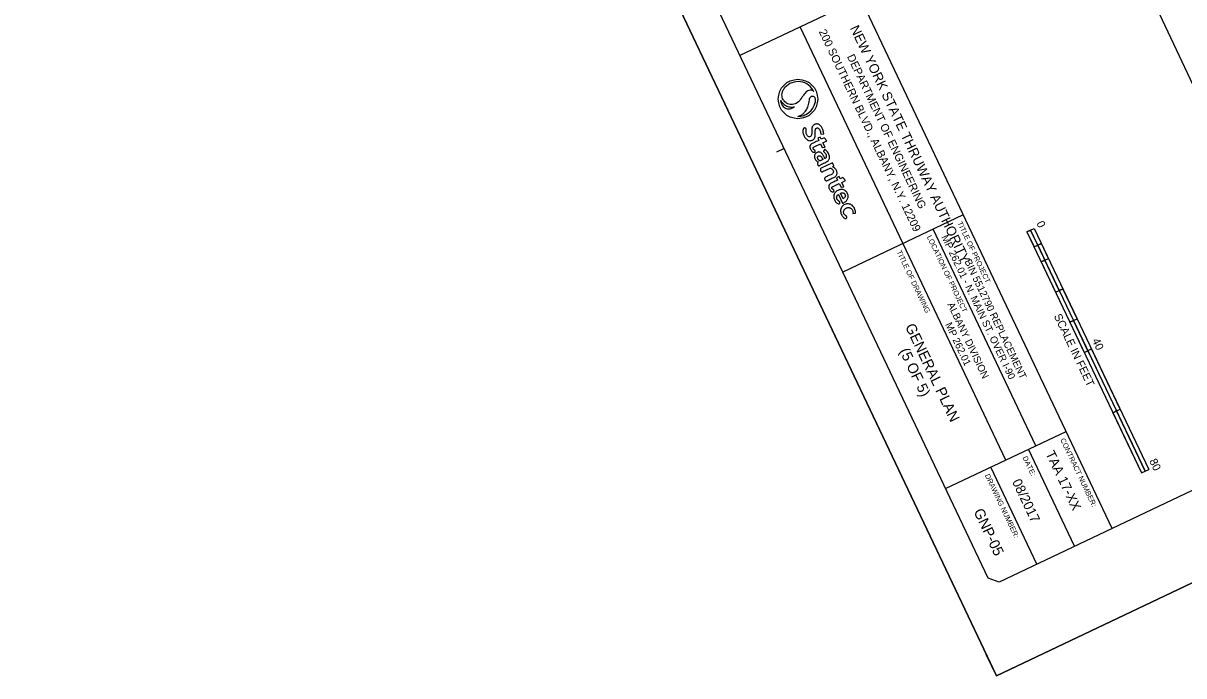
# Model space of a CAD drawing. Extents: x 1041072 to 1041761, y 1125784 to 1126587.
# Drawn here: x 1041071.6 to 1041419.5, y 1125783.8 to 1125979.4 of the extents above; entities that cross this region are included whole.
import ezdxf

# ---------------------------------------------------------------- set-up
doc = ezdxf.new("R2010")
doc.units = 0
for name, color, linetype in [('clip boundary', 7, 'Continuous'), ('G-ANNO-LOGO', 7, 'Continuous'), ('NSB_P', 7, 'Continuous'), ('O_Details_Text Title and Subtitle Proposed_P_T', 7, 'Continuous'), ('SHEET_BORDER', 7, 'Continuous'), ('SHEET_BORDER_CUT', 7, 'Continuous'), ('SHEET_BORDER_TEXT', 7, 'Continuous')]:
    doc.layers.add(name, color=color, linetype=linetype)

msp = doc.modelspace()

# ---------------------------------------------------------------- linework, layer by layer
at = {"layer": 'clip boundary'}
for points in [[(1041469.06, 1126586.8), (1041760.77, 1125972.54), (1041363.32, 1125783.79), (1041071.61, 1126398.04)], [(1041436.47, 1126509.64), (1041674.33, 1125994.72), (1041455.4, 1125890.75), (1041213.53, 1126403.1)]]:
    msp.add_lwpolyline(points, close=True, dxfattribs=at)
at = {"layer": 'G-ANNO-LOGO'}
for p, q in [((1041308.75, 1125942.33), (1041310.61, 1125943.2)), ((1041310.52, 1125945.25), (1041309.79, 1125944.91)), ((1041309.79, 1125944.91), (1041310.11, 1125944.23)), ((1041310.84, 1125944.59), (1041310.52, 1125945.25)), ((1041310.61, 1125943.2), (1041311.13, 1125942.09)), ((1041310.69, 1125946.11), (1041311.56, 1125946.21)), ((1041311.71, 1125945), (1041310.84, 1125944.59)), ((1041311.34, 1125943.54), (1041312.51, 1125944.09)), ((1041311.98, 1125942.18), (1041311.34, 1125943.54)), ((1041312.51, 1125944.09), (1041311.71, 1125945)), ((1041311.13, 1125942.09), (1041311.98, 1125942.18)), ((1041311.93, 1125941.61), (1041311.46, 1125941)), ((1041311.3, 1125938.5), (1041310.47, 1125938.11)), ((1041314.2, 1125937.51), (1041310.85, 1125935.92)), ((1041311.34, 1125934.9), (1041313.55, 1125935.95)), ((1041314.62, 1125936.63), (1041314.2, 1125937.51)), ((1041314.2, 1125936.36), (1041314.62, 1125936.63)), ((1041316.16, 1125933.39), (1041315.43, 1125933.04)), ((1041315.43, 1125933.04), (1041315.75, 1125932.37)), ((1041316.48, 1125932.72), (1041316.16, 1125933.39)), ((1041317.35, 1125933.14), (1041316.48, 1125932.72)), ((1041318.14, 1125932.22), (1041317.35, 1125933.14)), ((1041314.39, 1125930.47), (1041316.24, 1125931.33)), ((1041316.24, 1125931.33), (1041316.77, 1125930.22)), ((1041316.77, 1125930.22), (1041317.62, 1125930.31)), ((1041316.97, 1125931.67), (1041318.14, 1125932.22)), ((1041317.62, 1125930.31), (1041316.97, 1125931.67)), ((1041315.98, 1125928.07), (1041317.25, 1125925.41)), ((1041317.39, 1125926.78), (1041316.63, 1125928.38)), ((1041320.31, 1125922.31), (1041321.11, 1125922.4))]:
    msp.add_line(p, q, dxfattribs=at)
for points in [[(1041308.61, 1125958.79), (1041308.61, 1125958.79)], [(1041308.97, 1125955.65), (1041308.96, 1125955.65)]]:
    msp.add_lwpolyline(points, dxfattribs=at)
msp.add_circle((1041303.86, 1125956.65), 5.91, dxfattribs=at)
for start, end in [(24.1697, 139.0876), (24.1633, 24.1697), (182.5216, 186.8611), (269.1846, 348.8358)]:
    msp.add_arc((1041303.86, 1125956.65), 5.21, start, end, dxfattribs=at)
for points, degree in [([(1041308.61, 1125958.79), (1041308.53, 1125958.89), (1041308.35, 1125959.13), (1041307.82, 1125959.31), (1041307.12, 1125959.29), (1041306.48, 1125958.94), (1041305.95, 1125958.41), (1041305.5, 1125957.77), (1041304.99, 1125957.08), (1041304.54, 1125956.37), (1041304.02, 1125955.78), (1041303.37, 1125955.31), (1041302.62, 1125955.06), (1041301.87, 1125954.96), (1041301.09, 1125955.08), (1041300.42, 1125955.41), (1041299.91, 1125955.84), (1041299.52, 1125956.27), (1041299.25, 1125956.82), (1041299.05, 1125957.48), (1041299.04, 1125958.23), (1041299.28, 1125959.14), (1041299.67, 1125959.71), (1041299.92, 1125960.06)], 3), ([(1041303.78, 1125951.45), (1041303.97, 1125951.49), (1041304.31, 1125951.56), (1041304.8, 1125951.81), (1041305.22, 1125952.07), (1041305.56, 1125952.39), (1041305.96, 1125952.76), (1041306.34, 1125953.27), (1041306.64, 1125953.88), (1041306.91, 1125954.61), (1041307.06, 1125955.44), (1041307.28, 1125956.33), (1041307.42, 1125957.02), (1041307.79, 1125957.41), (1041308.13, 1125957.58), (1041308.44, 1125957.52), (1041308.71, 1125957.37), (1041308.88, 1125957.08), (1041308.98, 1125956.69), (1041309, 1125956.2), (1041308.98, 1125955.84), (1041308.97, 1125955.65)], 3), ([(1041308.61, 1125958.79), (1041308.61, 1125958.79), (1041308.61, 1125958.79), (1041308.61, 1125958.79)], 2), ([(1041298.66, 1125956.43), (1041298.7, 1125956.3), (1041298.8, 1125956.02), (1041299.11, 1125955.6), (1041299.48, 1125955.13), (1041299.98, 1125954.8), (1041300.49, 1125954.51), (1041301.11, 1125954.31), (1041301.76, 1125954.2), (1041302.36, 1125954.23), (1041302.69, 1125954.31), (1041302.85, 1125954.34)], 3), ([(1041302.85, 1125954.34), (1041302.74, 1125954.25), (1041302.48, 1125954.02), (1041301.98, 1125953.75), (1041301.38, 1125953.58), (1041300.75, 1125953.62), (1041300.1, 1125953.79), (1041299.58, 1125954.23), (1041299.17, 1125954.76), (1041298.87, 1125955.36), (1041298.75, 1125955.82), (1041298.69, 1125956.03)], 3), ([(1041311.56, 1125946.21), (1041311.56, 1125946.26), (1041311.56, 1125946.52), (1041311.47, 1125946.96), (1041311.3, 1125947.48), (1041311.12, 1125947.93), (1041310.9, 1125948.28), (1041310.66, 1125948.6), (1041310.37, 1125948.87), (1041309.99, 1125949.09), (1041309.58, 1125949.19), (1041309.21, 1125949.17), (1041308.91, 1125949.07), (1041308.66, 1125948.93), (1041308.44, 1125948.76), (1041308.28, 1125948.56), (1041308.15, 1125948.34), (1041308.06, 1125948.1), (1041308, 1125947.84), (1041307.97, 1125947.53), (1041307.96, 1125947.17), (1041307.96, 1125946.78), (1041307.98, 1125946.38), (1041307.97, 1125946.04), (1041307.89, 1125945.76), (1041307.8, 1125945.55), (1041307.62, 1125945.41), (1041307.44, 1125945.33), (1041307.2, 1125945.3), (1041306.94, 1125945.39), (1041306.7, 1125945.61), (1041306.5, 1125945.91), (1041306.35, 1125946.27), (1041306.26, 1125946.61), (1041306.27, 1125946.92), (1041306.26, 1125947.17), (1041306.32, 1125947.37), (1041306.31, 1125947.52), (1041306.3, 1125947.67), (1041306.23, 1125947.79), (1041306.13, 1125947.9), (1041305.99, 1125947.97), (1041305.81, 1125947.98), (1041305.66, 1125947.91), (1041305.53, 1125947.82), (1041305.43, 1125947.63), (1041305.31, 1125947.3), (1041305.3, 1125946.81), (1041305.4, 1125946.26), (1041305.61, 1125945.75), (1041305.83, 1125945.33), (1041306.05, 1125944.98), (1041306.31, 1125944.7), (1041306.62, 1125944.43), (1041307.04, 1125944.23), (1041307.48, 1125944.13), (1041307.9, 1125944.2), (1041308.25, 1125944.35), (1041308.54, 1125944.53), (1041308.73, 1125944.77), (1041308.91, 1125945.04), (1041308.99, 1125945.39), (1041309.05, 1125945.77), (1041309.05, 1125946.16), (1041309.05, 1125946.59), (1041309.03, 1125947.02), (1041309.05, 1125947.4), (1041309.14, 1125947.69), (1041309.28, 1125947.87), (1041309.46, 1125947.97), (1041309.66, 1125948), (1041309.87, 1125947.95), (1041310.05, 1125947.84), (1041310.23, 1125947.66), (1041310.38, 1125947.41), (1041310.49, 1125947.15), (1041310.57, 1125946.88), (1041310.63, 1125946.61), (1041310.67, 1125946.35), (1041310.68, 1125946.19), (1041310.69, 1125946.11)], 3), ([(1041310.11, 1125944.23), (1041309.46, 1125943.93), (1041308.77, 1125943.6), (1041308.01, 1125943.23), (1041307.84, 1125943.11), (1041307.62, 1125942.92), (1041307.52, 1125942.69), (1041307.45, 1125942.48), (1041307.42, 1125942.28), (1041307.45, 1125942), (1041307.58, 1125941.65), (1041307.76, 1125941.31), (1041307.97, 1125940.98), (1041308.23, 1125940.78), (1041308.48, 1125940.66), (1041308.7, 1125940.66), (1041308.86, 1125940.72), (1041308.98, 1125940.81), (1041309.03, 1125940.92), (1041309.04, 1125941.03), (1041309.01, 1125941.14), (1041308.96, 1125941.24), (1041308.88, 1125941.33), (1041308.76, 1125941.39), (1041308.63, 1125941.46), (1041308.51, 1125941.56), (1041308.41, 1125941.68), (1041308.35, 1125941.83), (1041308.36, 1125941.98), (1041308.41, 1125942.13), (1041308.56, 1125942.25), (1041308.68, 1125942.3), (1041308.75, 1125942.33)], 3), ([(1041311.91, 1125938.8), (1041311.88, 1125938.87), (1041311.77, 1125939.09), (1041311.57, 1125939.46), (1041311.34, 1125939.9), (1041311.04, 1125940.28), (1041310.69, 1125940.59), (1041310.24, 1125940.79), (1041309.75, 1125940.76), (1041309.37, 1125940.55), (1041309.06, 1125940.33), (1041308.87, 1125939.99), (1041308.76, 1125939.57), (1041308.8, 1125939.07), (1041309, 1125938.63), (1041309.25, 1125938.25), (1041309.5, 1125937.99), (1041309.77, 1125937.84), (1041309.92, 1125937.79), (1041310, 1125937.76)], 3), ([(1041310, 1125937.76), (1041309.96, 1125937.74), (1041309.88, 1125937.69), (1041309.79, 1125937.55), (1041309.71, 1125937.36), (1041309.71, 1125937.08), (1041309.83, 1125936.85), (1041309.98, 1125936.65), (1041310.2, 1125936.65), (1041310.37, 1125936.73), (1041310.58, 1125936.89), (1041311.2, 1125937.25), (1041311.9, 1125937.53), (1041312.63, 1125937.89), (1041312.94, 1125938.14), (1041313.17, 1125938.5), (1041313.31, 1125938.83), (1041313.32, 1125939.27), (1041313.23, 1125939.76), (1041313.01, 1125940.3), (1041312.71, 1125940.8), (1041312.35, 1125941.25), (1041312.06, 1125941.5), (1041311.93, 1125941.61)], 3), ([(1041310.47, 1125938.11), (1041310.44, 1125938.13), (1041310.32, 1125938.19), (1041310.13, 1125938.32), (1041309.91, 1125938.52), (1041309.77, 1125938.78), (1041309.72, 1125939.04), (1041309.75, 1125939.24), (1041309.82, 1125939.41), (1041309.94, 1125939.55), (1041310.09, 1125939.63), (1041310.26, 1125939.68), (1041310.46, 1125939.65), (1041310.63, 1125939.54), (1041310.81, 1125939.39), (1041310.96, 1125939.15), (1041311.1, 1125938.9), (1041311.22, 1125938.67), (1041311.28, 1125938.55), (1041311.3, 1125938.5)], 3), ([(1041311.46, 1125941), (1041311.51, 1125940.96), (1041311.65, 1125940.85), (1041311.84, 1125940.65), (1041312.05, 1125940.4), (1041312.2, 1125940.14), (1041312.32, 1125939.85), (1041312.36, 1125939.56), (1041312.34, 1125939.28), (1041312.23, 1125939.03), (1041312.07, 1125938.87), (1041311.95, 1125938.82), (1041311.91, 1125938.8)], 3), ([(1041310.85, 1125935.92), (1041310.81, 1125935.89), (1041310.72, 1125935.83), (1041310.58, 1125935.67), (1041310.53, 1125935.41), (1041310.65, 1125935.15), (1041310.8, 1125934.9), (1041311.04, 1125934.82), (1041311.22, 1125934.84), (1041311.3, 1125934.88), (1041311.34, 1125934.9)], 3), ([(1041313.55, 1125935.95), (1041313.57, 1125935.94), (1041313.67, 1125935.89), (1041313.86, 1125935.77), (1041314.11, 1125935.62), (1041314.33, 1125935.38), (1041314.46, 1125935.09), (1041314.51, 1125934.77), (1041314.4, 1125934.48), (1041314.21, 1125934.27), (1041313.92, 1125934.06), (1041313.43, 1125933.87), (1041312.83, 1125933.56), (1041312.31, 1125933.35), (1041311.98, 1125933.17), (1041311.85, 1125932.96), (1041311.81, 1125932.68), (1041311.93, 1125932.44), (1041312.1, 1125932.24), (1041312.33, 1125932.12), (1041312.63, 1125932.19), (1041313.1, 1125932.47), (1041313.71, 1125932.72), (1041314.36, 1125933.05), (1041314.79, 1125933.23), (1041315.13, 1125933.45), (1041315.33, 1125933.69), (1041315.51, 1125933.99), (1041315.57, 1125934.38), (1041315.57, 1125934.83), (1041315.39, 1125935.26), (1041315.18, 1125935.62), (1041314.91, 1125935.91), (1041314.63, 1125936.14), (1041314.37, 1125936.27), (1041314.24, 1125936.34), (1041314.2, 1125936.36)], 3), ([(1041315.75, 1125932.37), (1041315.09, 1125932.06), (1041314.41, 1125931.74), (1041313.64, 1125931.36), (1041313.47, 1125931.24), (1041313.26, 1125931.05), (1041313.15, 1125930.83), (1041313.09, 1125930.62), (1041313.06, 1125930.42), (1041313.09, 1125930.13), (1041313.21, 1125929.78), (1041313.39, 1125929.44), (1041313.6, 1125929.12), (1041313.86, 1125928.92), (1041314.11, 1125928.8), (1041314.33, 1125928.79), (1041314.5, 1125928.86), (1041314.62, 1125928.95), (1041314.66, 1125929.06), (1041314.67, 1125929.16), (1041314.64, 1125929.27), (1041314.59, 1125929.37), (1041314.52, 1125929.47), (1041314.4, 1125929.52), (1041314.27, 1125929.59), (1041314.15, 1125929.7), (1041314.04, 1125929.81), (1041313.99, 1125929.96), (1041314, 1125930.12), (1041314.05, 1125930.26), (1041314.19, 1125930.38), (1041314.31, 1125930.43), (1041314.39, 1125930.47)], 3), ([(1041317.25, 1125925.41), (1041317.35, 1125925.45), (1041317.61, 1125925.56), (1041318, 1125925.8), (1041318.41, 1125926.13), (1041318.66, 1125926.52), (1041318.85, 1125926.91), (1041318.92, 1125927.33), (1041318.89, 1125927.81), (1041318.7, 1125928.28), (1041318.48, 1125928.72), (1041318.15, 1125929.07), (1041317.77, 1125929.34), (1041317.32, 1125929.51), (1041316.86, 1125929.55), (1041316.41, 1125929.48), (1041315.98, 1125929.34), (1041315.54, 1125929.13), (1041315.18, 1125928.85), (1041314.87, 1125928.5), (1041314.65, 1125928.1), (1041314.55, 1125927.6), (1041314.55, 1125927.03), (1041314.77, 1125926.48), (1041315.01, 1125925.99), (1041315.29, 1125925.62), (1041315.61, 1125925.37), (1041315.93, 1125925.23), (1041316.19, 1125925.25), (1041316.36, 1125925.37), (1041316.46, 1125925.53), (1041316.43, 1125925.69), (1041316.38, 1125925.84), (1041316.25, 1125925.98), (1041316.04, 1125926.12), (1041315.8, 1125926.28), (1041315.61, 1125926.52), (1041315.49, 1125926.77), (1041315.43, 1125927.05), (1041315.48, 1125927.32), (1041315.55, 1125927.6), (1041315.71, 1125927.83), (1041315.86, 1125927.99), (1041315.95, 1125928.05), (1041315.98, 1125928.07)], 3), ([(1041316.63, 1125928.38), (1041316.66, 1125928.39), (1041316.74, 1125928.43), (1041316.9, 1125928.5), (1041317.13, 1125928.54), (1041317.4, 1125928.52), (1041317.66, 1125928.4), (1041317.88, 1125928.18), (1041318.02, 1125927.9), (1041318.07, 1125927.6), (1041318.03, 1125927.3), (1041317.84, 1125927.07), (1041317.62, 1125926.9), (1041317.46, 1125926.81), (1041317.39, 1125926.78)], 3), ([(1041321.11, 1125922.4), (1041321.11, 1125922.51), (1041321.13, 1125922.79), (1041321.04, 1125923.27), (1041320.84, 1125923.82), (1041320.51, 1125924.36), (1041320.08, 1125924.81), (1041319.57, 1125925.12), (1041319.01, 1125925.25), (1041318.45, 1125925.22), (1041317.89, 1125925.05), (1041317.39, 1125924.75), (1041317, 1125924.35), (1041316.76, 1125923.91), (1041316.62, 1125923.39), (1041316.63, 1125922.77), (1041316.81, 1125922.12), (1041317.11, 1125921.6), (1041317.44, 1125921.2), (1041317.78, 1125920.92), (1041318.11, 1125920.79), (1041318.33, 1125920.88), (1041318.48, 1125920.98), (1041318.53, 1125921.13), (1041318.54, 1125921.27), (1041318.49, 1125921.4), (1041318.39, 1125921.55), (1041318.19, 1125921.64), (1041318, 1125921.81), (1041317.8, 1125921.97), (1041317.63, 1125922.26), (1041317.51, 1125922.59), (1041317.53, 1125922.98), (1041317.65, 1125923.32), (1041317.84, 1125923.63), (1041318.14, 1125923.84), (1041318.44, 1125924.04), (1041318.81, 1125924.1), (1041319.16, 1125924.12), (1041319.48, 1125924.05), (1041319.77, 1125923.89), (1041320.01, 1125923.66), (1041320.19, 1125923.34), (1041320.32, 1125923), (1041320.37, 1125922.64), (1041320.33, 1125922.41), (1041320.31, 1125922.31)], 3)]:
    msp.add_open_spline(points, degree=degree, dxfattribs=at)
at = {"layer": 'NSB_P'}
for p, q in [((1041372.51, 1125916.84), (1041374.68, 1125917.87)), ((1041373.59, 1125917.35), (1041372.51, 1125916.84)), ((1041372.51, 1125916.84), (1041406.83, 1125844.57)), ((1041372.51, 1125916.84), (1041374.66, 1125912.32)), ((1041373.59, 1125917.35), (1041407.91, 1125845.09)), ((1041375.74, 1125912.84), (1041373.59, 1125917.35)), ((1041374.68, 1125917.87), (1041409, 1125845.6)), ((1041374.66, 1125912.32), (1041376.82, 1125913.35)), ((1041374.66, 1125912.32), (1041375.74, 1125912.84)), ((1041376.82, 1125913.35), (1041375.74, 1125912.84)), ((1041375.74, 1125912.84), (1041377.88, 1125908.32)), ((1041378.97, 1125908.83), (1041376.82, 1125913.35)), ((1041376.8, 1125907.8), (1041378.97, 1125908.83)), ((1041377.88, 1125908.32), (1041376.8, 1125907.8)), ((1041377.88, 1125908.32), (1041378.97, 1125908.83)), ((1041382.17, 1125899.29), (1041377.88, 1125908.32)), ((1041376.8, 1125907.8), (1041381.09, 1125898.77)), ((1041381.09, 1125898.77), (1041383.26, 1125899.8)), ((1041381.09, 1125898.77), (1041382.17, 1125899.29)), ((1041383.26, 1125899.8), (1041382.17, 1125899.29)), ((1041382.17, 1125899.29), (1041386.46, 1125890.25)), ((1041387.55, 1125890.77), (1041383.26, 1125899.8)), ((1041385.38, 1125889.74), (1041387.55, 1125890.77)), ((1041386.46, 1125890.25), (1041387.55, 1125890.77)), ((1041386.46, 1125890.25), (1041385.38, 1125889.74)), ((1041385.38, 1125889.74), (1041389.67, 1125880.7)), ((1041390.75, 1125881.22), (1041386.46, 1125890.25)), ((1041389.67, 1125880.7), (1041391.84, 1125881.73)), ((1041389.67, 1125880.7), (1041390.75, 1125881.22)), ((1041391.84, 1125881.73), (1041390.75, 1125881.22)), ((1041390.75, 1125881.22), (1041399.33, 1125863.15)), ((1041400.42, 1125863.67), (1041391.84, 1125881.73)), ((1041398.25, 1125862.64), (1041400.42, 1125863.67)), ((1041399.33, 1125863.15), (1041398.25, 1125862.64)), ((1041399.33, 1125863.15), (1041400.42, 1125863.67)), ((1041407.91, 1125845.09), (1041399.33, 1125863.15)), ((1041398.25, 1125862.64), (1041406.83, 1125844.57)), ((1041406.83, 1125844.57), (1041409, 1125845.6)), ((1041406.83, 1125844.57), (1041407.91, 1125845.09))]:
    msp.add_line(p, q, dxfattribs=at)
at = {"layer": 'SHEET_BORDER'}
for p, q in [((1041398.04, 1125827.96), (1041253.98, 1126131.3)), ((1041322.56, 1125986.88), (1041286.43, 1125969.72)), ((1041366.16, 1125848.45), (1041304.5, 1125978.3)), ((1041299.7, 1125941.78), (1041297.45, 1125940.7)), ((1041353.4, 1125921.96), (1041317.26, 1125904.8)), ((1041375.2, 1125852.74), (1041344.36, 1125917.67)), ((1041348.1, 1125839.87), (1041384.23, 1125857.03)), ((1041386.75, 1125822.59), (1041372.94, 1125851.67)), ((1041375.46, 1125817.23), (1041361.65, 1125846.31))]:
    msp.add_line(p, q, dxfattribs=at)
msp.add_lwpolyline([(1041364.16, 1125811.87), (1041360.83, 1125813.06), (1041092.72, 1126377.63), (1041093.9, 1126380.96), (1041468.21, 1126558.72), (1041471.54, 1126557.53), (1041739.66, 1125992.96), (1041738.47, 1125989.63)], close=True, dxfattribs=at)
at = {"layer": 'SHEET_BORDER_CUT'}
msp.add_lwpolyline([(1041071.61, 1126398.04), (1041363.32, 1125783.79), (1041760.77, 1125972.54), (1041469.06, 1126586.8)], close=True, dxfattribs=at)
msp.add_lwpolyline([(1041369.7, 1125786.82), (1041363.32, 1125783.79), (1041360.28, 1125790.18)], dxfattribs=at)
at = {"layer": 'SHEET_BORDER_TEXT'}
msp.add_line((1041363.32, 1125783.79), (1041363.32, 1125783.79), dxfattribs=at)

# ---------------------------------------------------------------- texts
at = {"layer": 'NSB_P'}
for s, p in [('0', (1041375.27, 1125919.41)), ('SCALE IN FEET', (1041380.51, 1125891.6)), ('40', (1041391.94, 1125884.31)), ('80', (1041409.1, 1125848.18))]:
    msp.add_text(s, height=2.4, rotation=295.4032, dxfattribs=at).set_placement(p)
at = {"layer": 'O_Details_Text Title and Subtitle Proposed_P_T'}
for s, height, p in [('GENERAL PLAN', 3.1248, (1041335.91, 1125888.47)), ('(5 OF 5)', 3.125, (1041334.19, 1125881.15)), ('GNP-05', 3.125, (1041356.43, 1125833.03))]:
    msp.add_text(s, height=height, rotation=295.4032, dxfattribs=at).set_placement(p)
at = {"layer": 'SHEET_BORDER'}
for s, height, p in [('200 SOUTHERN BLVD., ALBANY, N.Y. 12209', 2.4, (1041310.03, 1125976.86)), ('NEW YORK STATE THRUWAY AUTHORITY', 2.88, (1041319.37, 1125977.91)), ('DEPARTMENT OF ENGINEERING', 2.4, (1041318.48, 1125969.38)), ('TITLE OF PROJECT', 1.5625, (1041351.58, 1125919.5)), ('LOCATION OF PROJECT', 1.5625, (1041342.44, 1125915.35)), ('TITLE OF DRAWING', 1.5625, (1041333.37, 1125910.85)), ('CONTRACT NUMBER:', 1.5625, (1041382.42, 1125854.57)), ('DATE:', 1.562, (1041371.12, 1125849.21)), ('DRAWING NUMBER:', 1.5625, (1041359.83, 1125843.85))]:
    msp.add_text(s, height=height, rotation=295.4032, dxfattribs=at).set_placement(p)
at = {"layer": 'SHEET_BORDER_TEXT'}
for s, height, p in [('MP 262.01 - N. MAIN ST. OVER I-90', 2.16, (1041346.8, 1125915.3)), ('BIN 5512790 REPLACEMENT', 2.16, (1041353.71, 1125908)), ('ALBANY DIVISION', 2.16, (1041348.59, 1125895.09)), ('MP 262.01', 2.16, (1041347.92, 1125889.08)), ('TAA 17-XX', 2.88, (1041377.99, 1125850.41)), ('08/2017', 2.88, (1041367.98, 1125841.94))]:
    msp.add_text(s, height=height, rotation=295.4032, dxfattribs=at).set_placement(p)

doc.saveas('drawing.dxf')
